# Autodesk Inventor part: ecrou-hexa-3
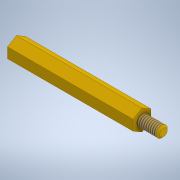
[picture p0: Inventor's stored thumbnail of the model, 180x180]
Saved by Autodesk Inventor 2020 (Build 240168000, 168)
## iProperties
Created: 2021-10
Part Number: ecrou-hexa-3
Material: Générique
Document SubType Name: Modeling
Designer: bruno
Density: 1 g/cm^3
Appearance: Or
Author: bruno
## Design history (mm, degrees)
sketch "Esquisse1"
  geometry: L1 (-2.887, 0)-(-1.443, 2.5); L2 (-1.443, 2.5)-(1.443, 2.5); L3 (1.443, 2.5)-(2.887, 0); L4 (2.887, 0)-(1.443, -2.5); L5 (1.443, -2.5)-(-1.443, -2.5); L6 (-1.443, -2.5)-(-2.887, 0); C1 r 1.5 at (0, 0); 2 further points
  constraints: 12 end point, 2 coincident, 1 centre point, 13 other
  dimensions: "d0" = 5 distance between parallel lines of L2 L5; "d1" = 3 diameter of C1
extrude "Extrusion1" new body sketch "Esquisse1" distance "d2" = 35; taper "d3" = 0 deg
feature "Filetage1" dims "d4" = 17, "d5" = 0
sketch "Esquisse2"
  geometry: C1 r 1.541 at (0, 0); 1 further point
  constraints: 1 centre point, 1 coincident
extrude "Extrusion2" join sketch "Esquisse2" distance "d6" = 6; taper "d7" = 0 deg
chamfer "Chanfrein1" distance "d8" = 0.5; stored, may be unused: second distance "d9" = 2, angle "d10" = 45 deg
feature "Filetage2" dims "d11" = 5.5, "d12" = 0
node "Solide1"
